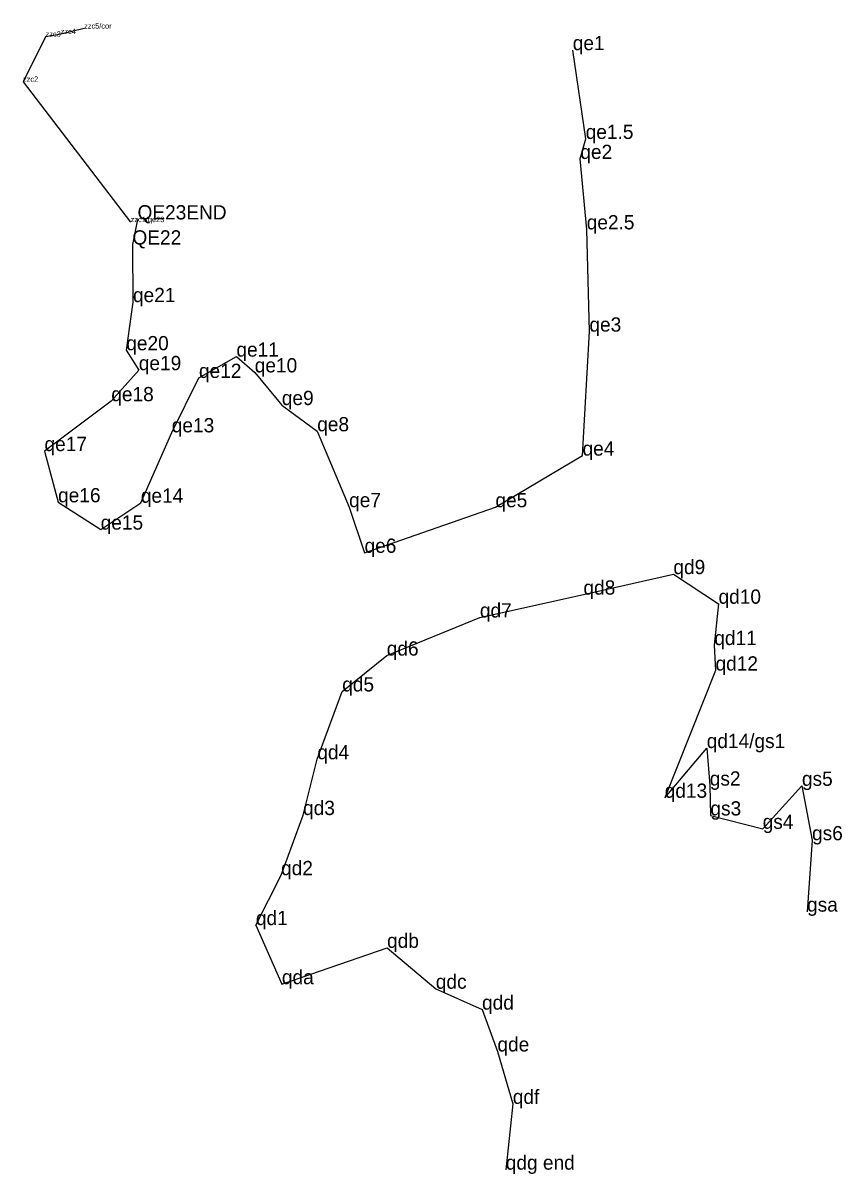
# Model space of a CAD drawing. Extents: x 2072529 to 2267990, y 436423 to 470008.
# Drawn here: x 2156651 to 2157110, y 439461 to 440106 of the extents above; entities that cross this region are included whole.
import ezdxf

# ---------------------------------------------------------------- set-up
doc = ezdxf.new("R2010")
doc.units = 0
doc.layers.add('Level 3', color=7, linetype='Continuous')
doc.layers.add('Old_Level_52', color=7, linetype='Continuous')

msp = doc.modelspace()

# ---------------------------------------------------------------- linework, layer by layer
at = {"layer": 'Level 3'}
for p, q in [((2156685.599, 440103.287), (2156685.599, 440103.287)), ((2156663.982, 440098.755), (2156663.982, 440098.755)), ((2156672.468, 440100.258), (2156672.468, 440100.258)), ((2156959.547, 440091.238), (2156959.547, 440091.238)), ((2156651.36, 440073.506), (2156651.36, 440073.506)), ((2156966.782, 440041.421), (2156966.782, 440041.421)), ((2156963.778, 440030.202), (2156963.778, 440030.202)), ((2156711.695, 439994.777), (2156711.695, 439994.777)), ((2156715.536, 439996.301), (2156715.536, 439996.301)), ((2156967.353, 439990.726), (2156967.353, 439990.726)), ((2156712.692, 439982.22), (2156712.692, 439982.22)), ((2156712.984, 439949.932), (2156712.984, 439949.932)), ((2156968.867, 439933.38), (2156968.867, 439933.38)), ((2156709.225, 439922.92), (2156709.225, 439922.92)), ((2156770.993, 439919.355), (2156770.993, 439919.355)), ((2156716.268, 439911.761), (2156716.268, 439911.761)), ((2156781.261, 439910.526), (2156781.261, 439910.526)), ((2156749.987, 439907.398), (2156749.987, 439907.398)), ((2156700.843, 439894.334), (2156700.843, 439894.334)), ((2156796.445, 439892.199), (2156796.445, 439892.199)), ((2156734.745, 439876.905), (2156734.745, 439876.905)), ((2156816.275, 439877.486), (2156816.275, 439877.486)), ((2156663.397, 439866.389), (2156663.397, 439866.389)), ((2156965.018, 439863.845), (2156965.018, 439863.845)), ((2156671.012, 439837.665), (2156671.012, 439837.665)), ((2156717.411, 439837.431), (2156717.411, 439837.431)), ((2156834.175, 439834.939), (2156834.175, 439834.939)), ((2156916.187, 439834.876), (2156916.187, 439834.876)), ((2156694.891, 439822.342), (2156694.891, 439822.342)), ((2156842.806, 439809.352), (2156842.806, 439809.352)), ((2157015.944, 439797.388), (2157015.944, 439797.388)), ((2156965.529, 439785.884), (2156965.529, 439785.884)), ((2157041.254, 439780.778), (2157041.254, 439780.778)), ((2156907.475, 439773.075), (2156907.475, 439773.075)), ((2157038.857, 439757.609), (2157038.857, 439757.609)), ((2156855.257, 439751.7), (2156855.257, 439751.7)), ((2157039.574, 439743.306), (2157039.574, 439743.306)), ((2156830.29, 439731.58), (2156830.29, 439731.58)), ((2157034.629, 439699.859), (2157034.629, 439699.859)), ((2156816.331, 439693.558), (2156816.331, 439693.558)), ((2157036.343, 439678.788), (2157036.343, 439678.788)), ((2157088.019, 439678.659), (2157088.019, 439678.659)), ((2157011.067, 439671.963), (2157011.067, 439671.963)), ((2156808.337, 439662.298), (2156808.337, 439662.298)), ((2157036.702, 439662.043), (2157036.702, 439662.043)), ((2157066.002, 439654.554), (2157066.002, 439654.554)), ((2157093.674, 439648.148), (2157093.674, 439648.148)), ((2156796.02, 439628.571), (2156796.02, 439628.571)), ((2157090.881, 439608.11), (2157090.881, 439608.11)), ((2156781.898, 439600.565), (2156781.898, 439600.565)), ((2156855.434, 439587.827), (2156855.434, 439587.827)), ((2156796.47, 439567.437), (2156796.47, 439567.437)), ((2156882.766, 439564.883), (2156882.766, 439564.883)), ((2156908.664, 439553.168), (2156908.664, 439553.168)), ((2156917.311, 439529.715), (2156917.311, 439529.715)), ((2156925.926, 439500.32), (2156925.926, 439500.32)), ((2156921.987, 439463.425), (2156921.987, 439463.425))]:
    msp.add_line(p, q, dxfattribs=at)
at = {"layer": 'Old_Level_52'}
for points in [[(2156685.599, 440103.287), (2156672.468, 440100.258), (2156663.982, 440098.755), (2156651.36, 440073.506), (2156711.695, 439994.777)], [(2156715.536, 439996.301), (2156712.692, 439982.22), (2156712.984, 439949.932), (2156709.225, 439922.92), (2156716.268, 439911.761), (2156700.843, 439894.334), (2156663.397, 439866.389), (2156671.012, 439837.665), (2156694.891, 439822.342), (2156717.411, 439837.431), (2156734.745, 439876.905), (2156749.987, 439907.398), (2156770.993, 439919.355), (2156781.261, 439910.526), (2156796.445, 439892.199), (2156816.275, 439877.486), (2156834.175, 439834.939), (2156842.806, 439809.352), (2156916.187, 439834.876), (2156965.018, 439863.845), (2156968.867, 439933.38), (2156967.353, 439990.726), (2156963.778, 440030.202), (2156966.782, 440041.421), (2156959.547, 440091.238)], [(2156781.898, 439600.565), (2156796.02, 439628.571), (2156808.337, 439662.298), (2156816.331, 439693.558), (2156830.29, 439731.58), (2156855.257, 439751.7), (2156907.475, 439773.075), (2156965.529, 439785.884), (2157015.944, 439797.388), (2157041.254, 439780.778), (2157038.857, 439757.609), (2157039.574, 439743.306), (2157011.067, 439671.963), (2157034.629, 439699.859), (2157036.343, 439678.788), (2157036.702, 439662.043), (2157066.002, 439654.554), (2157088.019, 439678.659), (2157093.674, 439648.148), (2157090.881, 439608.11)], [(2156781.898, 439600.565), (2156796.47, 439567.437), (2156855.434, 439587.827), (2156882.766, 439564.883), (2156908.664, 439553.168), (2156917.311, 439529.715), (2156925.926, 439500.32), (2156921.987, 439463.425)]]:
    msp.add_lwpolyline(points, dxfattribs=at)

# ---------------------------------------------------------------- texts
for s, height, p in [('zzc4', 3, (2156672.468, 440100.258)), ('zzc5/cor', 3, (2156685.599, 440103.287)), ('zzc3', 3, (2156663.982, 440098.755)), ('qe1', 8, (2156959.547, 440091.238)), ('zzc2', 3, (2156651.36, 440073.506)), ('qe1.5', 8, (2156966.782, 440041.421)), ('qe2', 8, (2156963.778, 440030.202)), ('QE23END', 8, (2156715.536, 439996.301)), ('zzc1/qe23', 3, (2156711.695, 439994.777)), ('qe2.5', 8, (2156967.353, 439990.726)), ('QE22', 8, (2156712.692, 439982.22)), ('qe21', 8, (2156712.984, 439949.932)), ('qe3', 8, (2156968.867, 439933.38)), ('qe20', 8, (2156709.225, 439922.92)), ('qe11', 8, (2156770.993, 439919.355)), ('qe19', 8, (2156716.268, 439911.761)), ('qe12', 8, (2156749.987, 439907.398)), ('qe10', 8, (2156781.261, 439910.526)), ('qe18', 8, (2156700.843, 439894.334)), ('qe9', 8, (2156796.445, 439892.199)), ('qe13', 8, (2156734.745, 439876.905)), ('qe8', 8, (2156816.275, 439877.486)), ('qe17', 8, (2156663.397, 439866.389)), ('qe4', 8, (2156965.018, 439863.845)), ('qe16', 8, (2156671.012, 439837.665)), ('qe14', 8, (2156717.411, 439837.431)), ('qe7', 8, (2156834.175, 439834.939)), ('qe5', 8, (2156916.187, 439834.876)), ('qe15', 8, (2156694.891, 439822.342)), ('qe6', 8, (2156842.806, 439809.352)), ('qd9', 8, (2157015.944, 439797.388)), ('qd8', 8, (2156965.529, 439785.884)), ('qd10', 8, (2157041.254, 439780.778)), ('qd7', 8, (2156907.475, 439773.075)), ('qd11', 8, (2157038.857, 439757.609)), ('qd6', 8, (2156855.257, 439751.7)), ('qd12', 8, (2157039.574, 439743.306)), ('qd5', 8, (2156830.29, 439731.58)), ('qd14/gs1', 8, (2157034.629, 439699.859)), ('qd4', 8, (2156816.331, 439693.558)), ('gs2', 8, (2157036.343, 439678.788)), ('gs5', 8, (2157088.019, 439678.659)), ('qd13', 8, (2157011.067, 439671.963)), ('qd3', 8, (2156808.337, 439662.298)), ('gs3', 8, (2157036.702, 439662.043)), ('gs4', 8, (2157066.002, 439654.554)), ('gs6', 8, (2157093.674, 439648.148)), ('qd2', 8, (2156796.02, 439628.571)), ('gsa', 8, (2157090.881, 439608.11)), ('qd1', 8, (2156781.898, 439600.565)), ('qdb', 8, (2156855.434, 439587.827)), ('qda', 8, (2156796.47, 439567.437)), ('qdc', 8, (2156882.766, 439564.883)), ('qdd', 8, (2156908.664, 439553.168)), ('qde', 8, (2156917.311, 439529.715)), ('qdf', 8, (2156925.926, 439500.32)), ('qdg end', 8, (2156921.987, 439463.425))]:
    msp.add_text(s, height=height).set_placement(p)

doc.saveas('drawing.dxf')
